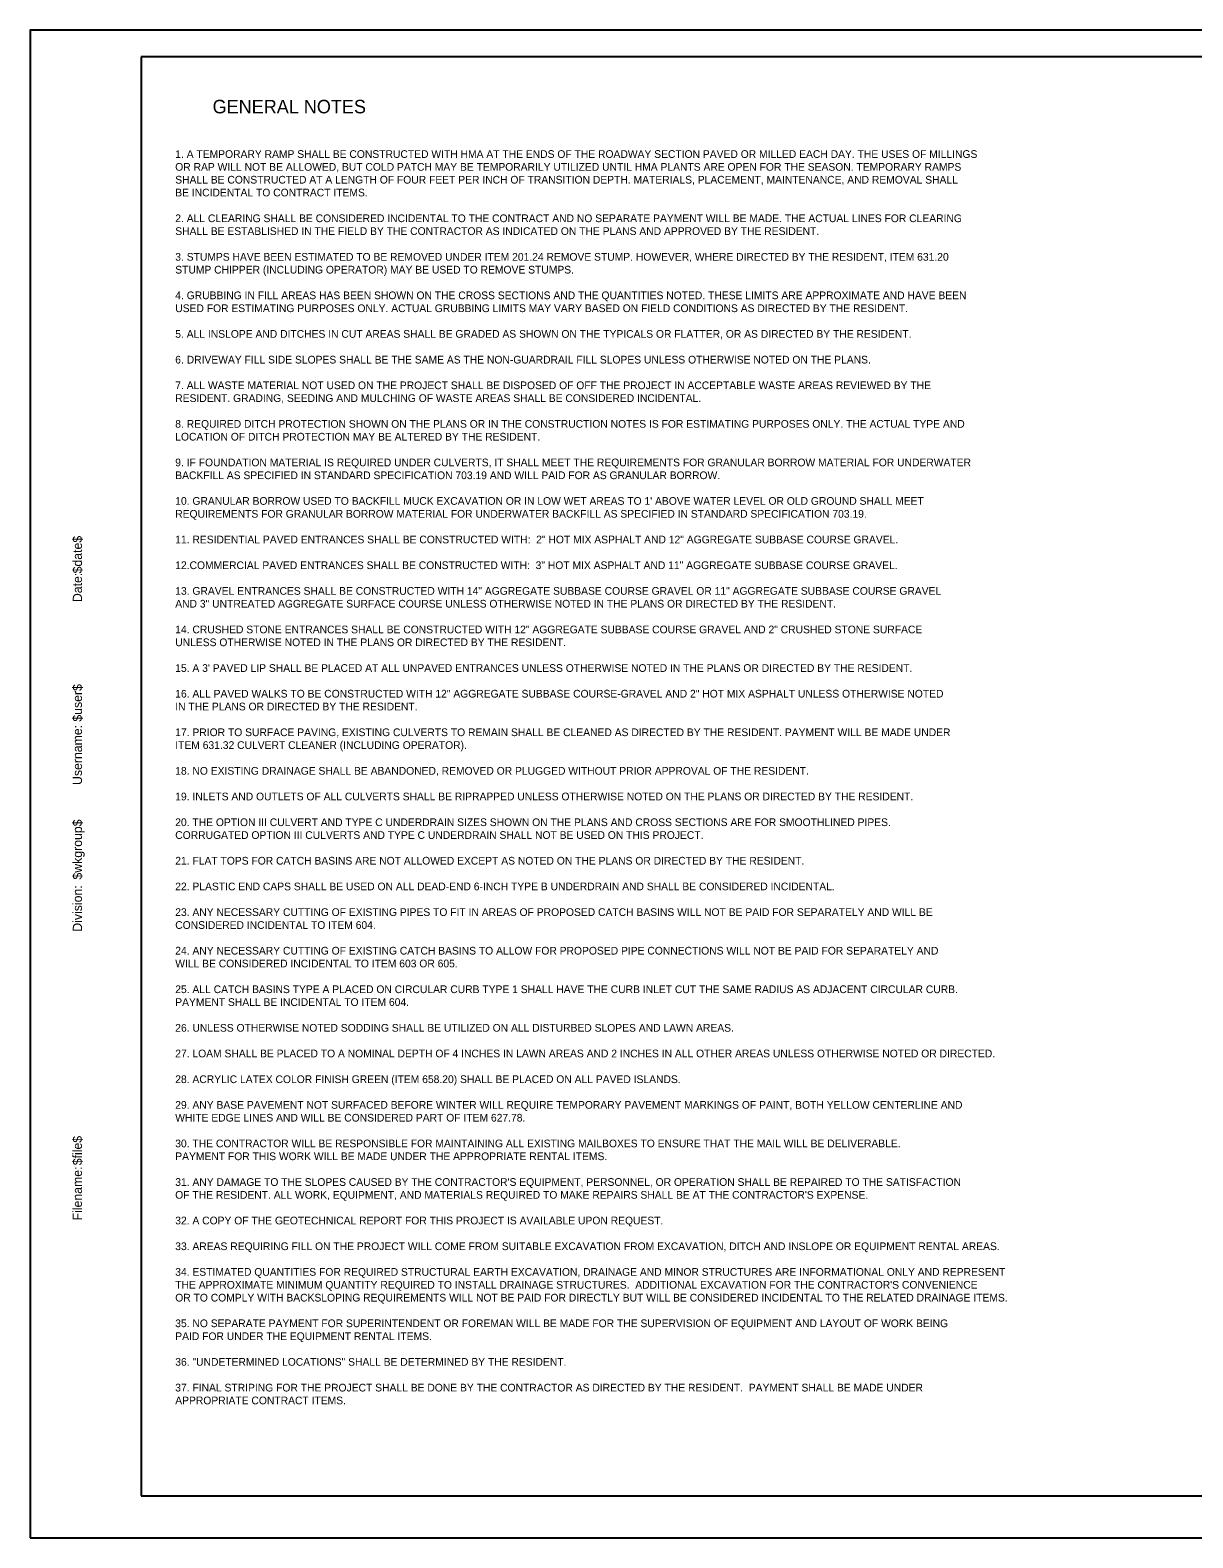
# Model space of a CAD drawing. Extents: x -0.13 to 5.88, y -0.37 to 1.78.
# Drawn here: x -0.135 to 1.279, y -0.051 to 1.782 of the extents above; entities that cross this region are included whole.
import ezdxf

# ---------------------------------------------------------------- set-up
doc = ezdxf.new("R2010")
doc.units = 0
for name, color, linetype in [('ANNOTATION', 7, 'Continuous'), ('BORDER', 7, 'Continuous'), ('PLOT BOUNDARY', 7, 'Continuous')]:
    doc.layers.add(name, color=color, linetype=linetype)

msp = doc.modelspace()

# ---------------------------------------------------------------- linework, layer by layer
at = {"layer": 'BORDER'}
for p, q in [((2.6667, 1.75), (0, 1.75)), ((0, 1.75), (0, 0)), ((0, 0), (2.6667, 0))]:
    msp.add_line(p, q, dxfattribs=at)
at = {"layer": 'PLOT BOUNDARY'}
msp.add_lwpolyline([(-0.1349, -0.051), (2.6984, -0.051), (2.6984, 1.7823), (-0.1349, 1.7823)], close=True, dxfattribs=at)

# ---------------------------------------------------------------- texts
at = {"layer": 'ANNOTATION'}
for s, height, p in [('GENERAL NOTES', 0.016404, (0.0869, 1.6812)), ('1. A TEMPORARY RAMP SHALL BE CONSTRUCTED WITH HMA AT THE ENDS OF THE ROADWAY SECTION PAVED OR MILLED EACH DAY. THE USES OF MILLINGS', 0.009375, (0.0415, 1.627)), ('OR RAP WILL NOT BE ALLOWED, BUT COLD PATCH MAY BE TEMPORARILY UTILIZED UNTIL HMA PLANTS ARE OPEN FOR THE SEASON. TEMPORARY RAMPS', 0.009375, (0.0415, 1.6114)), ('SHALL BE CONSTRUCTED AT A LENGTH OF FOUR FEET PER INCH OF TRANSITION DEPTH. MATERIALS, PLACEMENT, MAINTENANCE, AND REMOVAL SHALL', 0.009375, (0.0415, 1.5958)), ('BE INCIDENTAL TO CONTRACT ITEMS.', 0.009375, (0.0415, 1.5802)), ('2. ALL CLEARING SHALL BE CONSIDERED INCIDENTAL TO THE CONTRACT AND NO SEPARATE PAYMENT WILL BE MADE. THE ACTUAL LINES FOR CLEARING', 0.009375, (0.0415, 1.5489)), ('SHALL BE ESTABLISHED IN THE FIELD BY THE CONTRACTOR AS INDICATED ON THE PLANS AND APPROVED BY THE RESIDENT.', 0.009375, (0.0415, 1.5333)), ('3. STUMPS HAVE BEEN ESTIMATED TO BE REMOVED UNDER ITEM 201.24 REMOVE STUMP. HOWEVER, WHERE DIRECTED BY THE RESIDENT, ITEM 631.20', 0.009375, (0.0415, 1.502)), ('STUMP CHIPPER (INCLUDING OPERATOR) MAY BE USED TO REMOVE STUMPS.', 0.009375, (0.0415, 1.4864)), ('4. GRUBBING IN FILL AREAS HAS BEEN SHOWN ON THE CROSS SECTIONS AND THE QUANTITIES NOTED. THESE LIMITS ARE APPROXIMATE AND HAVE BEEN', 0.009375, (0.0415, 1.4552)), ('USED FOR ESTIMATING PURPOSES ONLY. ACTUAL GRUBBING LIMITS MAY VARY BASED ON FIELD CONDITIONS AS DIRECTED BY THE RESIDENT. ', 0.009375, (0.0415, 1.4395)), ('5. ALL INSLOPE AND DITCHES IN CUT AREAS SHALL BE GRADED AS SHOWN ON THE TYPICALS OR FLATTER, OR AS DIRECTED BY THE RESIDENT.', 0.009375, (0.0415, 1.4083)), ('6. DRIVEWAY FILL SIDE SLOPES SHALL BE THE SAME AS THE NON-GUARDRAIL FILL SLOPES UNLESS OTHERWISE NOTED ON THE PLANS.', 0.009375, (0.0415, 1.377)), ('7. ALL WASTE MATERIAL NOT USED ON THE PROJECT SHALL BE DISPOSED OF OFF THE PROJECT IN ACCEPTABLE WASTE AREAS REVIEWED BY THE', 0.009375, (0.0415, 1.3458)), ('RESIDENT. GRADING, SEEDING AND MULCHING OF WASTE AREAS SHALL BE CONSIDERED INCIDENTAL.', 0.009375, (0.0415, 1.3302)), ('8. REQUIRED DITCH PROTECTION SHOWN ON THE PLANS OR IN THE CONSTRUCTION NOTES IS FOR ESTIMATING PURPOSES ONLY. THE ACTUAL TYPE AND', 0.009375, (0.0415, 1.2989)), ('LOCATION OF DITCH PROTECTION MAY BE ALTERED BY THE RESIDENT.', 0.009375, (0.0415, 1.2833)), ('9. IF FOUNDATION MATERIAL IS REQUIRED UNDER CULVERTS, IT SHALL MEET THE REQUIREMENTS FOR GRANULAR BORROW MATERIAL FOR UNDERWATER', 0.009375, (0.0415, 1.252)), ('BACKFILL AS SPECIFIED IN STANDARD SPECIFICATION 703.19 AND WILL PAID FOR AS GRANULAR BORROW.', 0.009375, (0.0415, 1.2364)), ("10. GRANULAR BORROW USED TO BACKFILL MUCK EXCAVATION OR IN LOW WET AREAS TO 1' ABOVE WATER LEVEL OR OLD GROUND SHALL MEET", 0.009375, (0.0415, 1.2052)), ('REQUIREMENTS FOR GRANULAR BORROW MATERIAL FOR UNDERWATER BACKFILL AS SPECIFIED IN STANDARD SPECIFICATION 703.19.', 0.009375, (0.0415, 1.1895)), ('11. RESIDENTIAL PAVED ENTRANCES SHALL BE CONSTRUCTED WITH:  2" HOT MIX ASPHALT AND 12" AGGREGATE SUBBASE COURSE GRAVEL.', 0.009375, (0.0415, 1.1583)), ('12.COMMERCIAL PAVED ENTRANCES SHALL BE CONSTRUCTED WITH:  3" HOT MIX ASPHALT AND 11" AGGREGATE SUBBASE COURSE GRAVEL.', 0.009375, (0.0415, 1.127)), ('13. GRAVEL ENTRANCES SHALL BE CONSTRUCTED WITH 14" AGGREGATE SUBBASE COURSE GRAVEL OR 11" AGGREGATE SUBBASE COURSE GRAVEL', 0.009375, (0.0415, 1.0958)), ('AND 3" UNTREATED AGGREGATE SURFACE COURSE UNLESS OTHERWISE NOTED IN THE PLANS OR DIRECTED BY THE RESIDENT.', 0.009375, (0.0415, 1.0802)), ('14. CRUSHED STONE ENTRANCES SHALL BE CONSTRUCTED WITH 12" AGGREGATE SUBBASE COURSE GRAVEL AND 2" CRUSHED STONE SURFACE', 0.009375, (0.0415, 1.0489)), ('UNLESS OTHERWISE NOTED IN THE PLANS OR DIRECTED BY THE RESIDENT.', 0.009375, (0.0415, 1.0333)), ("15. A 3' PAVED LIP SHALL BE PLACED AT ALL UNPAVED ENTRANCES UNLESS OTHERWISE NOTED IN THE PLANS OR DIRECTED BY THE RESIDENT.", 0.009375, (0.0415, 1.002)), ('16. ALL PAVED WALKS TO BE CONSTRUCTED WITH 12" AGGREGATE SUBBASE COURSE-GRAVEL AND 2" HOT MIX ASPHALT UNLESS OTHERWISE NOTED', 0.009375, (0.0415, 0.9708)), ('IN THE PLANS OR DIRECTED BY THE RESIDENT.', 0.009375, (0.0415, 0.9552)), ('17. PRIOR TO SURFACE PAVING, EXISTING CULVERTS TO REMAIN SHALL BE CLEANED AS DIRECTED BY THE RESIDENT. PAYMENT WILL BE MADE UNDER', 0.009375, (0.0415, 0.9239)), ('ITEM 631.32 CULVERT CLEANER (INCLUDING OPERATOR).', 0.009375, (0.0415, 0.9083)), ('18. NO EXISTING DRAINAGE SHALL BE ABANDONED, REMOVED OR PLUGGED WITHOUT PRIOR APPROVAL OF THE RESIDENT.', 0.009375, (0.0415, 0.877)), ('19. INLETS AND OUTLETS OF ALL CULVERTS SHALL BE RIPRAPPED UNLESS OTHERWISE NOTED ON THE PLANS OR DIRECTED BY THE RESIDENT.', 0.009375, (0.0415, 0.8458)), ('20. THE OPTION III CULVERT AND TYPE C UNDERDRAIN SIZES SHOWN ON THE PLANS AND CROSS SECTIONS ARE FOR SMOOTHLINED PIPES.', 0.009375, (0.0415, 0.8145)), ('CORRUGATED OPTION III CULVERTS AND TYPE C UNDERDRAIN SHALL NOT BE USED ON THIS PROJECT.', 0.009375, (0.0415, 0.7989)), ('21. FLAT TOPS FOR CATCH BASINS ARE NOT ALLOWED EXCEPT AS NOTED ON THE PLANS OR DIRECTED BY THE RESIDENT.', 0.009375, (0.0415, 0.7677)), ('22. PLASTIC END CAPS SHALL BE USED ON ALL DEAD-END 6-INCH TYPE B UNDERDRAIN AND SHALL BE CONSIDERED INCIDENTAL.', 0.009375, (0.0415, 0.7364)), ('23. ANY NECESSARY CUTTING OF EXISTING PIPES TO FIT IN AREAS OF PROPOSED CATCH BASINS WILL NOT BE PAID FOR SEPARATELY AND WILL BE', 0.009375, (0.0415, 0.7052)), ('CONSIDERED INCIDENTAL TO ITEM 604.', 0.009375, (0.0415, 0.6895)), ('24. ANY NECESSARY CUTTING OF EXISTING CATCH BASINS TO ALLOW FOR PROPOSED PIPE CONNECTIONS WILL NOT BE PAID FOR SEPARATELY AND', 0.009375, (0.0415, 0.6583)), ('WILL BE CONSIDERED INCIDENTAL TO ITEM 603 OR 605.', 0.009375, (0.0415, 0.6427)), ('25. ALL CATCH BASINS TYPE A PLACED ON CIRCULAR CURB TYPE 1 SHALL HAVE THE CURB INLET CUT THE SAME RADIUS AS ADJACENT CIRCULAR CURB.', 0.009375, (0.0415, 0.6114)), ('PAYMENT SHALL BE INCIDENTAL TO ITEM 604.', 0.009375, (0.0415, 0.5958)), ('26. UNLESS OTHERWISE NOTED SODDING SHALL BE UTILIZED ON ALL DISTURBED SLOPES AND LAWN AREAS.', 0.009375, (0.0415, 0.5645)), ('27. LOAM SHALL BE PLACED TO A NOMINAL DEPTH OF 4 INCHES IN LAWN AREAS AND 2 INCHES IN ALL OTHER AREAS UNLESS OTHERWISE NOTED OR DIRECTED.', 0.009375, (0.0415, 0.5333)), ('28. ACRYLIC LATEX COLOR FINISH GREEN (ITEM 658.20) SHALL BE PLACED ON ALL PAVED ISLANDS.', 0.009375, (0.0415, 0.502)), ('29. ANY BASE PAVEMENT NOT SURFACED BEFORE WINTER WILL REQUIRE TEMPORARY PAVEMENT MARKINGS OF PAINT, BOTH YELLOW CENTERLINE AND', 0.009375, (0.0415, 0.4708)), ('WHITE EDGE LINES AND WILL BE CONSIDERED PART OF ITEM 627.78.', 0.009375, (0.0415, 0.4552)), ('30. THE CONTRACTOR WILL BE RESPONSIBLE FOR MAINTAINING ALL EXISTING MAILBOXES TO ENSURE THAT THE MAIL WILL BE DELIVERABLE.', 0.009375, (0.0415, 0.4239)), ('PAYMENT FOR THIS WORK WILL BE MADE UNDER THE APPROPRIATE RENTAL ITEMS.', 0.009375, (0.0415, 0.4083)), ("31. ANY DAMAGE TO THE SLOPES CAUSED BY THE CONTRACTOR'S EQUIPMENT, PERSONNEL, OR OPERATION SHALL BE REPAIRED TO THE SATISFACTION", 0.009375, (0.0415, 0.377)), ("OF THE RESIDENT. ALL WORK, EQUIPMENT, AND MATERIALS REQUIRED TO MAKE REPAIRS SHALL BE AT THE CONTRACTOR'S EXPENSE. ", 0.009375, (0.0415, 0.3614)), ('32. A COPY OF THE GEOTECHNICAL REPORT FOR THIS PROJECT IS AVAILABLE UPON REQUEST.  ', 0.009375, (0.0415, 0.3302)), ('33. AREAS REQUIRING FILL ON THE PROJECT WILL COME FROM SUITABLE EXCAVATION FROM EXCAVATION, DITCH AND INSLOPE OR EQUIPMENT RENTAL AREAS.', 0.009375, (0.0415, 0.2989)), ('34. ESTIMATED QUANTITIES FOR REQUIRED STRUCTURAL EARTH EXCAVATION, DRAINAGE AND MINOR STRUCTURES ARE INFORMATIONAL ONLY AND REPRESENT', 0.009375, (0.0415, 0.2677)), ("THE APPROXIMATE MINIMUM QUANTITY REQUIRED TO INSTALL DRAINAGE STRUCTURES.  ADDITIONAL EXCAVATION FOR THE CONTRACTOR'S CONVENIENCE", 0.009375, (0.0415, 0.252)), ('OR TO COMPLY WITH BACKSLOPING REQUIREMENTS WILL NOT BE PAID FOR DIRECTLY BUT WILL BE CONSIDERED INCIDENTAL TO THE RELATED DRAINAGE ITEMS.  ', 0.009375, (0.0415, 0.2364)), ('35. NO SEPARATE PAYMENT FOR SUPERINTENDENT OR FOREMAN WILL BE MADE FOR THE SUPERVISION OF EQUIPMENT AND LAYOUT OF WORK BEING', 0.009375, (0.0415, 0.2052)), ('PAID FOR UNDER THE EQUIPMENT RENTAL ITEMS.', 0.009375, (0.0415, 0.1895)), ('36. "UNDETERMINED LOCATIONS" SHALL BE DETERMINED BY THE RESIDENT.', 0.009375, (0.0415, 0.1583)), ('37. FINAL STRIPING FOR THE PROJECT SHALL BE DONE BY THE CONTRACTOR AS DIRECTED BY THE RESIDENT.  PAYMENT SHALL BE MADE UNDER', 0.009375, (0.0415, 0.127)), ('APPROPRIATE CONTRACT ITEMS.', 0.009375, (0.0415, 0.1114))]:
    msp.add_text(s, height=height, dxfattribs=at).set_placement(p)
at = {"layer": 'BORDER'}
for s, p in [('$date$', (-0.0719, 1.1218)), ('Date:', (-0.0719, 1.0869)), ('$user$', (-0.0719, 0.9415)), ('Username:', (-0.0719, 0.8645)), ('$wkgroup$', (-0.0719, 0.7495)), ('Division:', (-0.0719, 0.6861)), ('$file$', (-0.0719, 0.4021)), ('Filename:', (-0.0719, 0.335))]:
    msp.add_text(s, height=0.01116, rotation=90, dxfattribs=at).set_placement(p)

doc.saveas('drawing.dxf')
